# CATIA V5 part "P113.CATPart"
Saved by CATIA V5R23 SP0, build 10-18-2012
Part number: P113
Definition: Axe du plateau
Bounding box of the stored display mesh (mm): x -19.995 to 19.995, y -19.979 to 19.979, z 0 to 43
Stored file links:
  C:\wamp\www\COURS\CONCEPTION GMP1\TITRE 02-SEMESTRE 2\03-TP7-PRESSE MECANIQUE\eleve\P113.CATPart
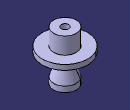
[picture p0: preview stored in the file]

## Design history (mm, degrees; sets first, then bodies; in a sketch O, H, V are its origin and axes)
Body1 (main body)
  Sketch1 on yz-plane, origin (0, 0, 0), H (0, 1, 0), V (0, 0, 1)
    line L1 (0, 0) -> (-10, 0)
    line L2 (-10, 0) -> (-10, 5)
    line L3 (-10, 5) -> (-5, 18)
    point P3 (-5, 18)
    line L4 (-5, 18) -> (-10, 18)
    point P4 (-10, 18)
    line L5 (-10, 18) -> (-10, 24)
    line L6 (-10, 24) -> (-20, 24)
    line L7 (-20, 24) -> (-20, 28.5)
    line L8 (-20, 28.5) -> (-10, 28.5)
    point P8 (-10, 28.5)
    line L9 (-10, 28.5) -> (-10, 43)
    line L10 (-10, 43) -> (0, 43)
    point P10 (0, 43)
    distance L2 V = 10
    distance P3 V = 5
    distance L1 L4 = 18
    distance L6 L4 = 6
    length L9 = 14.5
    distance L7 V = 20
    length L7 = 4.5
    length L2 = 5
    horizontal: L1 H, L4 H, L6 H, L8 H, L10 H
    vertical: L2 V, L5 V, L7 V, L9 V
    coincidence: P4 L2, P8 L2, P10 V
  Shaft1: profile Sketch1, axis Sketch1.V, angle 360
  Sketch2 on face of Shaft1, origin (0, 0, 43), H (1, 0, 0), V (0, 1, 0)
    point P1 (0, 0)
  Hole1: placed by Sketch2, at (0, 0, 43) direction (0, 0, -1), diameter 6.647, depth 18, V-bottom angle 120, threaded "M8", thread diameter 8, thread depth 12, pitch 1.25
